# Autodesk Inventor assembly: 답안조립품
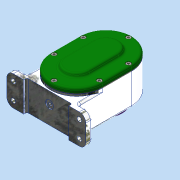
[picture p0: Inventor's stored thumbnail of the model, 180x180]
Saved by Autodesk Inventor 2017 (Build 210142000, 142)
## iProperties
Part Number: 답안조립품
Material: 일반
Document SubType Name: Assembly
Designer: MRC
Author: MRC
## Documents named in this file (19)
- C:\Users\MRC\Desktop\710609V1004\답안조립품.iam
- C:\Users\MRC\Desktop\710609V1004\본체.ipt
- C:\Users\MRC\Desktop\710609V1004\개스킷 A.ipt
- C:\Users\MRC\Desktop\710609V1004\개스킷 B.ipt
- C:\Users\MRC\Desktop\710609V1004\베어링 6001.ipt
- 베어링 6001.ipt
- C:\Users\MRC\Desktop\710609V1004\베어링 6002.ipt
- 베어링 6002.ipt
- C:\Users\MRC\Desktop\710609V1004\볼트 M4.ipt
- C:\Users\MRC\Desktop\710609V1004\스퍼기어 A.ipt
- C:\Users\MRC\Desktop\710609V1004\스퍼기어 B.ipt
- C:\Users\MRC\Desktop\710609V1004\오일 실 12 22 7.ipt
- C:\Users\MRC\Desktop\710609V1004\축 A.ipt
- C:\Users\MRC\Desktop\710609V1004\축 B.ipt
- C:\Users\MRC\Desktop\710609V1004\칼라.ipt
- C:\Users\MRC\Desktop\710609V1004\커버 A.ipt
- C:\Users\MRC\Desktop\710609V1004\커버 B.ipt
- C:\Users\MRC\Desktop\710609V1004\키 4 x 4 x 12.ipt
- C:\Users\MRC\Desktop\710609V1004\키 5 x 5 x 12.ipt
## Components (2 placed, 2 different names)
1. 개스킷 A:1
2. 개스킷 B:1
